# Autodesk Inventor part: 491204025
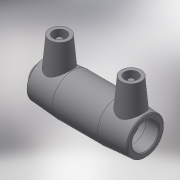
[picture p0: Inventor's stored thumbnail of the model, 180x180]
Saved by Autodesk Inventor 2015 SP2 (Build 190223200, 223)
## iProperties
Created: 2017-06
Part Number: 491204025
Material: Generic
Description: PLASSON END CAP 25
Document SubType Name: Modeling
Designer: KIM
Mass: 38.9236 g
Surface Area: 152.394 cm^2
Volume: 38.9236 cm^3
Density: 1 g/cm^3
Appearance: Default
Author: KIM
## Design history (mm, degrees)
derived "491204.ipt"
feature "Solid1::491204.ipt"
tag "TaggingFeature1"
body "Solid1"
other parameters: "d0" = 82, "d1" = 25, "d2" = 36, "d4" = 23, "d5" = 32.4, "d6" = 23.75, "d7" = 25, "d8" = 168 deg, "d10" = 16, "d11" = 5.33333, "d13" = 73.6, "d14" = 17.6296, "d17" = 23.75, "d18" = 25, "d19" = 3.52592, "d20" = 168 deg, "d22" = 33.84, "d23" = 36, "d24" = 32.8248, "d25" = 135 deg, "d26" = 33.12, "d27" = 135 deg, "d29" = 37, "d30" = 15, "d31" = 29.44, "d34" = 5 deg, "d35" = 15, "d39" = 5 deg, "d41" = 4, "d42" = 14, "d43" = 0, "d45" = 4, "d46" = 14, "d47" = 0, "d48" = 92, "d49" = 1, "d52" = 1.656, "d53" = 27.5, "d54" = 1.656, "d56" = 2.5, "d57" = 0.75, "d60" = 13.8, "d61" = 0.5, "d63" = 92, "d64" = 1, "d67" = 5, "d68" = 27.5, "d69" = 1.84, "d70" = 0, "d71" = 1.656, "d72" = 3, "d73" = 0, "d74" = 11.6, "d75" = 3.86667, "d76" = 3, "d77" = 0, "d_" = 25, "L_" = 92, "D_" = 36, "A_" = 37, "d_2" = 12, "L_0" = 82, "d55" = 2.5
